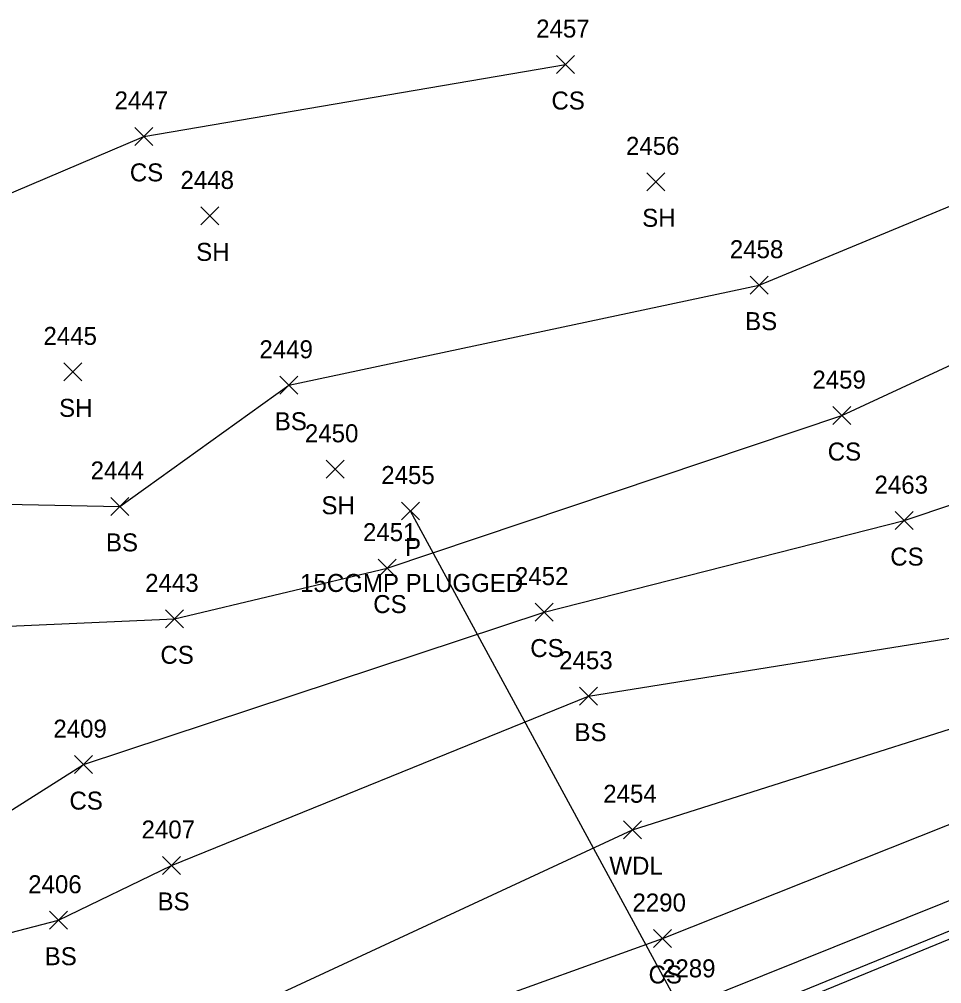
# Model space of a CAD drawing. Extents: x 1502194 to 1507887, y 142265 to 144150.
# Drawn here: x 1506739.4 to 1506842, y 143562.8 to 143670.1 of the extents above; entities that cross this region are included whole.
import ezdxf

# ---------------------------------------------------------------- set-up
doc = ezdxf.new("R2010")
doc.units = 0
for name, color, linetype in [('D_A', 7, 'Continuous'), ('D_C', 7, 'Continuous'), ('D_I', 7, 'Continuous'), ('D_TIC', 7, 'Continuous'), ('DCP', 7, 'Continuous'), ('L_A', 7, 'Continuous'), ('L_I', 7, 'Continuous'), ('L_TIC', 7, 'Continuous'), ('LAWA', 7, 'Continuous'), ('LELB', 7, 'Continuous'), ('PSP', 7, 'Continuous'), ('RGR', 7, 'Continuous')]:
    doc.layers.add(name, color=color, linetype=linetype)

msp = doc.modelspace()

# ---------------------------------------------------------------- linework, layer by layer
at = {"layer": 'D_TIC'}
for points in [[(1506781.88, 143614.38), (1506783.88, 143616.38)], [(1506783.88, 143614.38), (1506781.88, 143616.38)]]:
    msp.add_lwpolyline(points, dxfattribs=at)
at = {"layer": 'DCP'}
msp.add_lwpolyline([(1506814.95, 143556.34), (1506782.88, 143615.38)], dxfattribs=at)
at = {"layer": 'L_TIC'}
for points in [[(1506799.11, 143664.02), (1506801.11, 143666.02)], [(1506801.11, 143664.02), (1506799.11, 143666.02)], [(1506752.22, 143656.03), (1506754.22, 143658.03)], [(1506754.22, 143656.03), (1506752.22, 143658.03)], [(1506809.15, 143650.98), (1506811.15, 143652.98)], [(1506811.15, 143650.98), (1506809.15, 143652.98)], [(1506759.55, 143647.19), (1506761.55, 143649.19)], [(1506761.55, 143647.19), (1506759.55, 143649.19)], [(1506820.65, 143639.49), (1506822.65, 143641.49)], [(1506822.65, 143639.49), (1506820.65, 143641.49)], [(1506744.31, 143629.85), (1506746.31, 143631.85)], [(1506746.31, 143629.85), (1506744.31, 143631.85)], [(1506768.34, 143628.36), (1506770.34, 143630.36)], [(1506770.34, 143628.36), (1506768.34, 143630.36)], [(1506829.83, 143624.99), (1506831.83, 143626.99)], [(1506831.83, 143624.99), (1506829.83, 143626.99)], [(1506773.48, 143619.02), (1506775.48, 143621.02)], [(1506775.48, 143619.02), (1506773.48, 143621.02)], [(1506749.56, 143614.89), (1506751.56, 143616.89)], [(1506751.56, 143614.89), (1506749.56, 143616.89)], [(1506836.79, 143613.31), (1506838.79, 143615.31)], [(1506838.79, 143613.31), (1506836.79, 143615.31)], [(1506779.29, 143608.03), (1506781.29, 143610.03)], [(1506781.29, 143608.03), (1506779.29, 143610.03)], [(1506796.75, 143603.14), (1506798.75, 143605.14)], [(1506798.75, 143603.14), (1506796.75, 143605.14)], [(1506755.62, 143602.39), (1506757.62, 143604.39)], [(1506757.62, 143602.39), (1506755.62, 143604.39)], [(1506801.67, 143593.79), (1506803.67, 143595.79)], [(1506803.67, 143593.79), (1506801.67, 143595.79)], [(1506745.5, 143586.18), (1506747.5, 143588.18)], [(1506747.5, 143586.18), (1506745.5, 143588.18)], [(1506806.57, 143578.94), (1506808.57, 143580.94)], [(1506808.57, 143578.94), (1506806.57, 143580.94)], [(1506755.3, 143574.97), (1506757.3, 143576.97)], [(1506757.3, 143574.97), (1506755.3, 143576.97)], [(1506742.74, 143568.88), (1506744.74, 143570.88)], [(1506744.74, 143568.88), (1506742.74, 143570.88)], [(1506809.91, 143566.85), (1506811.91, 143568.85)], [(1506811.91, 143566.85), (1506809.91, 143568.85)]]:
    msp.add_lwpolyline(points, dxfattribs=at)
at = {"layer": 'LAWA'}
msp.add_lwpolyline([(1506522.71, 143485.76), (1506572.06, 143503.17), (1506623.68, 143515.47), (1506667.22, 143531.44), (1506692.19, 143539.75), (1506705.6, 143543.12), (1506724.44, 143544.97), (1506738.66, 143547.16), (1506749.81, 143546.64), (1506758.77, 143557.3), (1506807.57, 143579.94), (1506846.79, 143592.4), (1506896.99, 143614.38)], dxfattribs=at)
at = {"layer": 'LELB'}
for points in [[(1506693.67, 143643.35), (1506706.7, 143647.28), (1506735.24, 143649.4), (1506753.22, 143657.03), (1506800.11, 143665.02)], [(1506705.82, 143601.14), (1506721.55, 143616.46), (1506750.56, 143615.89), (1506769.34, 143629.36), (1506821.65, 143640.49), (1506874.45, 143662.34)], [(1506624.13, 143555.62), (1506640.38, 143556.63), (1506654.94, 143561), (1506672.72, 143565.79), (1506679.72, 143575.67), (1506695.05, 143577.62), (1506699.47, 143577.91), (1506701.5, 143575.19), (1506703.76, 143575.39), (1506707.13, 143577.97), (1506705.55, 143581.26), (1506716.61, 143587.23), (1506735.68, 143602.47), (1506756.62, 143603.39), (1506780.29, 143609.03), (1506830.83, 143625.99), (1506880.34, 143648.95)], [(1506517.85, 143501.34), (1506567.89, 143522.62), (1506612.11, 143536.7), (1506661.61, 143547.98), (1506681.76, 143559.52), (1506695.53, 143572.24), (1506704.85, 143572.91), (1506725.52, 143573.91), (1506746.5, 143587.18), (1506797.75, 143604.14), (1506837.79, 143614.31), (1506888.27, 143631.28)], [(1506520.26, 143493.12), (1506571.84, 143512.42), (1506617.89, 143527.46), (1506663.2, 143542.3), (1506684.6, 143550.02), (1506709.64, 143561.03), (1506743.74, 143569.88), (1506756.3, 143575.97), (1506802.67, 143594.79), (1506845.42, 143601.65), (1506896.99, 143614.38)], [(1506527.12, 143479.02), (1506576.48, 143493.75), (1506624.1, 143506.32), (1506671.3, 143519.58), (1506718.08, 143535.11), (1506766.47, 143551.82), (1506810.91, 143567.85), (1506852.21, 143584.27), (1506899, 143603.69)], [(1506528.28, 143476.03), (1506576.44, 143487.76), (1506625.32, 143500.66), (1506672.84, 143513.46), (1506720.65, 143528.12), (1506770.21, 143545.68), (1506814.12, 143560.53), (1506853.98, 143576.57), (1506901.25, 143597.01)]]:
    msp.add_lwpolyline(points, dxfattribs=at)
at = {"layer": 'PSP'}
msp.add_lwpolyline([(1506528.1, 143471.41), (1506577.64, 143482.92), (1506624.2, 143495.08), (1506674.01, 143508.85), (1506722.38, 143522.96), (1506769.18, 143539.06), (1506814.23, 143556.06), (1506856.23, 143573.29), (1506902.36, 143593.17)], dxfattribs=at)
at = {"layer": 'RGR'}
msp.add_lwpolyline([(1506528.09, 143471.93), (1506577.33, 143484.15), (1506624.99, 143496.57), (1506673.85, 143509.85), (1506721.49, 143524.09), (1506768.89, 143540.23), (1506815.19, 143557.42), (1506856.11, 143574.12), (1506902.1, 143593.94)], dxfattribs=at)

# ---------------------------------------------------------------- texts
at = {"layer": 'D_A'}
msp.add_text('P', height=2, dxfattribs=at).set_placement((1506782.26, 143610.38))
at = {"layer": 'D_C'}
msp.add_text('15CGMP PLUGGED', height=2, dxfattribs=at).set_placement((1506770.59, 143606.38))
at = {"layer": 'D_I'}
msp.add_text('2455', height=2, dxfattribs=at).set_placement((1506779.62, 143618.38))
at = {"layer": 'L_A'}
for s, p in [('CS', (1506798.55, 143660.02)), ('CS', (1506751.66, 143652.03)), ('SH', (1506808.64, 143646.98)), ('SH', (1506759.04, 143643.19)), ('BS', (1506820.09, 143635.49)), ('SH', (1506743.79, 143625.85)), ('BS', (1506767.78, 143624.36)), ('CS', (1506829.28, 143620.99)), ('SH', (1506772.97, 143615.02)), ('BS', (1506749, 143610.89)), ('CS', (1506836.23, 143609.31)), ('CS', (1506778.73, 143604.03)), ('CS', (1506755.06, 143598.39)), ('CS', (1506796.19, 143599.14)), ('BS', (1506801.11, 143589.79)), ('CS', (1506744.94, 143582.18)), ('WDL', (1506804.99, 143574.94)), ('BS', (1506754.74, 143570.97)), ('BS', (1506742.19, 143564.88)), ('CS', (1506809.35, 143562.85))]:
    msp.add_text(s, height=2, dxfattribs=at).set_placement(p)
at = {"layer": 'L_I'}
for s, p in [('2457', (1506796.85, 143668.02)), ('2447', (1506749.96, 143660.03)), ('2456', (1506806.84, 143654.98)), ('2448', (1506757.29, 143651.19)), ('2458', (1506818.39, 143643.49)), ('2445', (1506742.05, 143633.85)), ('2449', (1506766.07, 143632.36)), ('2459', (1506827.57, 143628.99)), ('2450', (1506771.13, 143623.02)), ('2444', (1506747.3, 143618.89)), ('2463', (1506834.48, 143617.31)), ('2451', (1506777.59, 143612.03)), ('2452', (1506794.49, 143607.14)), ('2443', (1506753.36, 143606.39)), ('2453', (1506799.41, 143597.79)), ('2409', (1506743.15, 143590.18)), ('2454', (1506804.31, 143582.94)), ('2407', (1506752.96, 143578.97)), ('2406', (1506740.35, 143572.88)), ('2290', (1506807.56, 143570.85)), ('2289', (1506810.85, 143563.53))]:
    msp.add_text(s, height=2, dxfattribs=at).set_placement(p)

doc.saveas('drawing.dxf')
